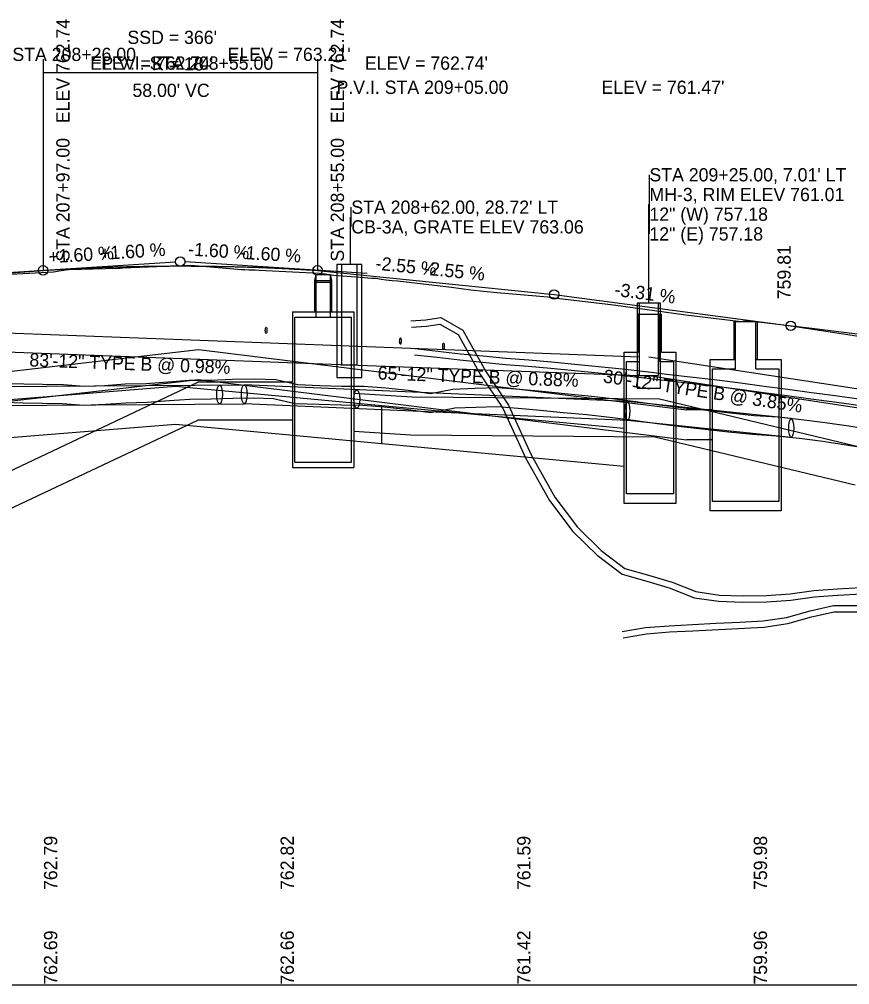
# Model space of a CAD drawing. Extents: x 1833473 to 1837132, y 704683 to 706683.
# Drawn here: x 1834502.8 to 1834678.2, y 705682.6 to 705886.7 of the extents above; entities that cross this region are included whole.
import ezdxf

# ---------------------------------------------------------------- set-up
doc = ezdxf.new("R2010")
doc.units = 0
for name, color, linetype in [('DR_P_Storm_Sewer', 7, 'Continuous'), ('DR_P_Text', 7, 'Continuous'), ('GK_Cells', 7, 'Continuous'), ('PF_P_Grade_Line', 7, 'Continuous'), ('PF_P_Text', 7, 'Continuous'), ('PF_X_Ground_Line', 7, 'Continuous'), ('PF_X_Text', 7, 'Continuous'), ('UT_P_Electric', 7, 'Continuous'), ('UT_P_Telecom', 7, 'Continuous'), ('UT_P_Water', 7, 'Continuous'), ('UT_X_Electric', 7, 'Continuous'), ('UT_X_Telecom', 7, 'Continuous'), ('UT_X_Water', 7, 'Continuous')]:
    doc.layers.add(name, color=color, linetype=linetype)

msp = doc.modelspace()

# ---------------------------------------------------------------- linework, layer by layer
at = {"layer": 'DR_P_Storm_Sewer'}
for p, q in [((1834572.78, 705834.89), (1834572.78, 705834.89)), ((1834635.78, 705826.69), (1834635.78, 705826.69)), ((1834486.63, 705820.89), (1834572.5, 705817.65)), ((1834486.63, 705816.89), (1834572.5, 705813.65)), ((1834572.5, 705817.65), (1834633.75, 705815.37)), ((1834635.78, 705815.37), (1834665.78, 705810.77)), ((1834572.5, 705813.65), (1834633.75, 705811.37)), ((1834635.78, 705811.37), (1834665.78, 705806.77)), ((1834665.78, 705810.77), (1834792.35, 705791.41)), ((1834665.78, 705806.77), (1834792.35, 705787.41))]:
    msp.add_line(p, q, dxfattribs=at)
for points in [[(1834569.88, 705834.89), (1834569.88, 705810.98), (1834575.14, 705810.98), (1834575.14, 705834.89), (1834569.88, 705834.89)], [(1834570.88, 705834.89), (1834570.88, 705813.65), (1834574.13, 705813.65), (1834574.13, 705834.89)], [(1834633.33, 705826.69), (1834633.33, 705808.7), (1834638.23, 705808.7), (1834638.23, 705826.69), (1834633.33, 705826.69)], [(1834633.75, 705826.69), (1834633.75, 705811.37), (1834637.81, 705811.37), (1834637.81, 705826.69)]]:
    msp.add_lwpolyline(points, dxfattribs=at)
at = {"layer": 'DR_P_Text'}
for p, q in [((1834635.85, 705853.82), (1834635.85, 705841.32)), ((1834572.85, 705846.97), (1834572.85, 705842.81))]:
    msp.add_line(p, q, dxfattribs=at)
for points in [[(1834635.78, 705826.69), (1834635.78, 705847.57), (1834635.85, 705847.57)], [(1834572.78, 705834.89), (1834572.78, 705844.89), (1834572.85, 705844.89)]]:
    msp.add_lwpolyline(points, dxfattribs=at)
at = {"layer": 'GK_Cells'}
msp.add_line((1833710.78, 705682.65), (1834910.78, 705682.65), dxfattribs=at)
msp.add_line((1833710.78, 705682.65), (1834910.78, 705682.65), dxfattribs=at)
at = {"layer": 'PF_P_Grade_Line'}
for p, q in [((1834457.78, 705829.97), (1834507.78, 705833.62)), ((1834565.78, 705833.62), (1834615.78, 705828.52)), ((1834615.78, 705828.52), (1834665.78, 705821.9)), ((1834665.78, 705821.9), (1834800.78, 705801.3))]:
    msp.add_line(p, q, dxfattribs=at)
msp.add_spline([(1834507.78, 705833.62), (1834508.94, 705833.69), (1834510.1, 705833.76), (1834511.26, 705833.83), (1834512.42, 705833.89), (1834513.58, 705833.95), (1834514.74, 705834.01), (1834515.9, 705834.07), (1834517.06, 705834.12), (1834518.22, 705834.17), (1834519.38, 705834.21), (1834520.54, 705834.26), (1834521.7, 705834.3), (1834522.86, 705834.33), (1834524.02, 705834.37), (1834525.18, 705834.4), (1834526.34, 705834.43), (1834527.5, 705834.45), (1834528.66, 705834.47), (1834529.82, 705834.49), (1834530.98, 705834.51), (1834532.14, 705834.52), (1834533.3, 705834.53), (1834534.46, 705834.54), (1834535.62, 705834.55), (1834536.78, 705834.55), (1834537.94, 705834.55), (1834539.1, 705834.54), (1834540.26, 705834.53), (1834541.42, 705834.52), (1834542.58, 705834.51), (1834543.74, 705834.49), (1834544.9, 705834.47), (1834546.06, 705834.45), (1834547.22, 705834.43), (1834548.38, 705834.4), (1834549.54, 705834.37), (1834550.7, 705834.33), (1834551.86, 705834.3), (1834553.02, 705834.26), (1834554.18, 705834.21), (1834555.34, 705834.17), (1834556.5, 705834.12), (1834557.66, 705834.07), (1834558.82, 705834.01), (1834559.98, 705833.95), (1834561.14, 705833.89), (1834562.3, 705833.83), (1834563.46, 705833.76), (1834564.62, 705833.69), (1834565.78, 705833.62)], degree=3, dxfattribs=at)
at = {"layer": 'PF_P_Text'}
for p, q in [((1834507.78, 705878.27), (1834507.78, 705833.62)), ((1834565.78, 705878.27), (1834565.78, 705833.62)), ((1834507.78, 705875.47), (1834565.78, 705875.47)), ((1834497.26, 705832.95), (1834535.78, 705835.41)), ((1834576.3, 705832.95), (1834537.78, 705835.41))]:
    msp.add_line(p, q, dxfattribs=at)
for centre in [(1834536.78, 705835.47), (1834507.78, 705833.62), (1834565.78, 705833.62), (1834615.78, 705828.52), (1834665.78, 705821.9)]:
    msp.add_circle(centre, 1, dxfattribs=at)
at = {"layer": 'PF_X_Ground_Line'}
for points in [[(1834498.28, 705832.64), (1834510.01, 705833.28), (1834510.85, 705833.43), (1834511.6, 705833.59), (1834512.07, 705833.68), (1834512.5, 705833.74), (1834512.9, 705833.78), (1834513.22, 705833.8), (1834523.55, 705834.09), (1834524.11, 705834.11), (1834524.63, 705834.13), (1834538.92, 705834.69), (1834547.31, 705834.03), (1834548.87, 705833.86), (1834549.74, 705833.8), (1834550.44, 705833.78), (1834551.24, 705833.76), (1834551.54, 705833.75), (1834551.85, 705833.74), (1834552.6, 705833.71), (1834553.46, 705833.68), (1834566.16, 705833.02), (1834566.74, 705832.96), (1834567.47, 705832.86), (1834568.28, 705832.75), (1834569.26, 705832.62), (1834570.13, 705832.52), (1834575.73, 705832.09), (1834576.39, 705832.02), (1834577.25, 705832), (1834578.15, 705831.97), (1834579.22, 705831.79), (1834580.26, 705831.62), (1834581.53, 705831.51), (1834582.78, 705831.4), (1834594.13, 705830.06), (1834598.17, 705829.52)], [(1834598.17, 705829.52), (1834603.7, 705828.97), (1834614.43, 705828), (1834615.82, 705827.84), (1834628.34, 705826.36), (1834643.65, 705824.23), (1834655.33, 705822.79), (1834656.45, 705822.99), (1834657.76, 705822.85), (1834667.83, 705821.66), (1834670.23, 705821.4), (1834680.37, 705820.12)]]:
    msp.add_lwpolyline(points, dxfattribs=at)
at = {"layer": 'UT_P_Electric'}
for p, q in [((1834653.81, 705814.8), (1834653.81, 705822.8)), ((1834653.81, 705822.8), (1834658.73, 705822.8)), ((1834654.14, 705812.8), (1834654.14, 705822.8)), ((1834658.39, 705812.8), (1834658.39, 705822.8)), ((1834658.73, 705814.8), (1834658.73, 705822.8)), ((1834392.11, 705799.79), (1834540.6, 705816.88)), ((1834540.6, 705816.88), (1834643.77, 705804.12)), ((1834649.27, 705784.8), (1834649.27, 705812.8)), ((1834649.27, 705812.8), (1834654.14, 705812.8)), ((1834658.39, 705812.8), (1834663.27, 705812.8)), ((1834663.27, 705812.8), (1834663.27, 705784.8)), ((1834392.11, 705793.46), (1834540.64, 705810.55)), ((1834540.64, 705810.55), (1834643.77, 705797.79)), ((1834649.27, 705804.12), (1834643.77, 705804.12)), ((1834649.27, 705797.79), (1834643.77, 705797.79)), ((1834663.27, 705784.8), (1834649.27, 705784.8))]:
    msp.add_line(p, q, dxfattribs=at)
msp.add_lwpolyline([(1834658.39, 705814.8), (1834663.77, 705814.8), (1834663.77, 705782.8), (1834648.77, 705782.8), (1834648.77, 705814.8), (1834654.14, 705814.8)], dxfattribs=at)
at = {"layer": 'UT_P_Telecom'}
for p, q in [((1834633.53, 705816.36), (1834633.53, 705824.36)), ((1834633.53, 705824.36), (1834638.45, 705824.36)), ((1834633.86, 705814.36), (1834633.86, 705824.36)), ((1834638.11, 705814.36), (1834638.11, 705824.36)), ((1834638.45, 705816.36), (1834638.45, 705824.36)), ((1834630.57, 705784.36), (1834630.57, 705816.36)), ((1834630.57, 705816.36), (1834633.53, 705816.36)), ((1834638.45, 705816.36), (1834641.49, 705816.36)), ((1834641.49, 705816.36), (1834641.49, 705784.36)), ((1834631.07, 705786.36), (1834631.07, 705814.36)), ((1834631.07, 705814.36), (1834633.86, 705814.36)), ((1834638.11, 705814.36), (1834640.99, 705814.36)), ((1834640.99, 705814.36), (1834640.99, 705786.36)), ((1834410.78, 705799.07), (1834535.78, 705809.12)), ((1834535.78, 705809.12), (1834630.55, 705800.27)), ((1834579.3, 705805.06), (1834579.3, 705797.06)), ((1834410.78, 705791.07), (1834535.78, 705801.12)), ((1834535.78, 705801.12), (1834630.55, 705792.27)), ((1834640.99, 705786.36), (1834631.07, 705786.36)), ((1834641.49, 705784.36), (1834630.57, 705784.36))]:
    msp.add_line(p, q, dxfattribs=at)
at = {"layer": 'UT_P_Water'}
for p, q in [((1834460.78, 705808.8), (1834550.3, 705809.43)), ((1834631.26, 705805.89), (1834550.3, 705809.43)), ((1834460.8, 705804.8), (1834550.3, 705805.43)), ((1834631.26, 705801.89), (1834550.3, 705805.43)), ((1834665.88, 705802.33), (1834631.26, 705805.89)), ((1834665.89, 705798.32), (1834631.26, 705801.89))]:
    msp.add_line(p, q, dxfattribs=at)
for centre, major_axis, ratio in [((1834545.09, 705807.39), (0, -2), 0.304231), ((1834550.3, 705807.43), (0, -2), 0.304231), ((1834574.1, 705806.39), (0, -2), 0.304231), ((1834631.26, 705803.86), (0, -1.96), 0.27031), ((1834665.89, 705800.29), (0, -1.96), 0.27031)]:
    msp.add_ellipse(centre, major_axis=major_axis, ratio=ratio, dxfattribs=at)
at = {"layer": 'UT_X_Electric'}
for p, q in [((1834565.25, 705831.5), (1834565.49, 705832.75)), ((1834565.49, 705823.73), (1834565.49, 705832.75)), ((1834565.49, 705832.75), (1834568.49, 705832.75)), ((1834568.49, 705832.75), (1834568.49, 705823.73)), ((1834568.49, 705832.75), (1834568.71, 705831.49)), ((1834565.25, 705824.83), (1834565.25, 705831.5)), ((1834565.25, 705831.5), (1834568.71, 705831.49)), ((1834565.25, 705831.09), (1834568.69, 705831.09)), ((1834568.71, 705831.49), (1834568.71, 705824.83)), ((1834560.49, 705824.83), (1834573.48, 705824.83)), ((1834560.49, 705824.83), (1834560.49, 705791.93)), ((1834573.48, 705824.83), (1834573.48, 705791.93)), ((1834560.99, 705823.73), (1834572.99, 705823.73)), ((1834560.99, 705793.07), (1834560.99, 705823.73)), ((1834572.99, 705793.07), (1834572.99, 705823.73)), ((1834500.49, 705791.07), (1834540.49, 705809.98)), ((1834560.49, 705809.98), (1834540.49, 705809.98)), ((1834500.49, 705783.06), (1834540.49, 705801.96)), ((1834560.49, 705801.96), (1834540.49, 705801.96)), ((1834560.49, 705791.93), (1834573.48, 705791.93)), ((1834560.99, 705793.07), (1834572.99, 705793.07))]:
    msp.add_line(p, q, dxfattribs=at)
for points in [[(1834585.53, 705822.92), (1834588.66, 705823.16), (1834591.86, 705823.67), (1834596.52, 705821.01), (1834601.38, 705812.23), (1834606.11, 705805.13), (1834610.92, 705794.63), (1834615.93, 705785.71), (1834620.75, 705779.34), (1834625.75, 705774.43), (1834630.75, 705770.62), (1834635.75, 705769.18), (1834640.74, 705767.71), (1834645.73, 705765.73), (1834650.71, 705765), (1834655.7, 705764.82), (1834660.69, 705764.92), (1834665.68, 705765.27), (1834670.67, 705765.93), (1834675.65, 705766.3), (1834680.62, 705766.58)], [(1834585.63, 705821.59), (1834588.82, 705821.84), (1834591.6, 705822.28), (1834595.53, 705820.04), (1834600.24, 705811.54), (1834604.94, 705804.48), (1834609.73, 705794.02), (1834614.82, 705784.98), (1834619.75, 705778.45), (1834624.88, 705773.42), (1834630.14, 705769.41), (1834635.37, 705767.9), (1834640.3, 705766.45), (1834645.38, 705764.43), (1834650.59, 705763.67), (1834655.69, 705763.48), (1834660.75, 705763.59), (1834665.81, 705763.94), (1834670.8, 705764.61), (1834675.74, 705764.97), (1834680.75, 705765.26)], [(1834573.48, 705807.65), (1834585.78, 705806.89)], [(1834585.78, 705806.89), (1834638.05, 705806.44), (1834681.25, 705796.1)], [(1834573.48, 705799.63), (1834585.5, 705798.89)], [(1834585.5, 705798.89), (1834637.07, 705798.45), (1834679.39, 705788.32)], [(1834630.16, 705757.26), (1834635.13, 705758.15), (1834640.09, 705758.52), (1834645.05, 705758.78), (1834650.02, 705759.04), (1834654.98, 705759.3), (1834659.95, 705759.56), (1834664.91, 705760.28), (1834669.88, 705761.65), (1834674.84, 705762.81), (1834679.83, 705762.78)], [(1834630.39, 705755.94), (1834635.29, 705756.82), (1834640.17, 705757.19), (1834645.12, 705757.45), (1834660.08, 705758.23), (1834665.19, 705758.98), (1834670.2, 705760.36), (1834674.99, 705761.47), (1834679.82, 705761.45)]]:
    msp.add_lwpolyline(points, dxfattribs=at)
for centre in [(1834583.3, 705818.67), (1834592.41, 705817.6)]:
    msp.add_ellipse(centre, major_axis=(0, -0.667), ratio=0.250004, dxfattribs=at)
at = {"layer": 'UT_X_Telecom'}
for points in [[(1834586.41, 705817.09), (1834591.2, 705816.57), (1834596, 705816.01), (1834600.81, 705815.56), (1834605.61, 705815.08), (1834610.41, 705814.69), (1834615.22, 705814.26), (1834620.19, 705813.8), (1834625.19, 705813.32), (1834630.19, 705812.8), (1834635.19, 705812.22), (1834640.19, 705811.64), (1834645.19, 705811.06), (1834650.19, 705810.47), (1834655.19, 705809.85), (1834660.19, 705809.13), (1834665.19, 705808.48), (1834670.19, 705807.81), (1834675.19, 705807.15), (1834680.19, 705806.49)], [(1834586.27, 705815.77), (1834591.05, 705815.25), (1834595.86, 705814.68), (1834600.68, 705814.23), (1834605.49, 705813.75), (1834610.3, 705813.36), (1834615.1, 705812.93), (1834620.07, 705812.48), (1834625.06, 705811.99), (1834630.05, 705811.48), (1834645.03, 705809.74), (1834650.03, 705809.14), (1834655.01, 705808.53), (1834660.01, 705807.81), (1834665.02, 705807.16), (1834670.01, 705806.49), (1834675.01, 705805.83), (1834680.01, 705805.16)]]:
    msp.add_lwpolyline(points, dxfattribs=at)
msp.add_ellipse((1834554.92, 705820.93), major_axis=(0, -0.667), ratio=0.250004, dxfattribs=at)
at = {"layer": 'UT_X_Water'}
for points in [[(1834499.89, 705809.74), (1834503.71, 705809.63), (1834507.67, 705809.57), (1834512.07, 705809.49), (1834516.45, 705809.16), (1834520.79, 705809.31), (1834525.12, 705809.62), (1834529.6, 705809.73), (1834534.12, 705810.07), (1834538.66, 705810.4), (1834543.21, 705810.44), (1834547.78, 705810.64), (1834552.37, 705810.67), (1834556.98, 705810.53), (1834561.61, 705809.47), (1834566.25, 705809.31), (1834570.9, 705809.17), (1834575.56, 705809.14), (1834580.25, 705808.77), (1834584.95, 705808.27), (1834589.65, 705807.62), (1834594.36, 705808.54), (1834599.07, 705808.69), (1834603.79, 705808.88), (1834608.51, 705808.5), (1834613.23, 705808.08), (1834618.08, 705807.57), (1834623.08, 705807.12), (1834628.08, 705806.56), (1834633.08, 705805.89)], [(1834499.59, 705805.75), (1834503.61, 705805.63), (1834507.61, 705805.57), (1834511.89, 705805.49), (1834516.37, 705805.16), (1834521, 705805.32), (1834525.31, 705805.62), (1834529.8, 705805.74), (1834534.41, 705806.08), (1834538.82, 705806.4), (1834543.31, 705806.44), (1834547.88, 705806.64), (1834552.32, 705806.67), (1834556.47, 705806.54), (1834561.09, 705805.48), (1834566.12, 705805.31), (1834570.83, 705805.17), (1834575.39, 705805.14), (1834579.88, 705804.78), (1834584.46, 705804.3), (1834589.76, 705803.57), (1834594.81, 705804.55), (1834599.22, 705804.69), (1834603.71, 705804.87), (1834608.18, 705804.51), (1834612.84, 705804.1), (1834617.69, 705803.58), (1834622.68, 705803.14), (1834627.59, 705802.59), (1834632.55, 705801.93)], [(1834633.08, 705805.89), (1834638.08, 705805.22), (1834643.08, 705804.59), (1834648.08, 705804.04), (1834653.08, 705803.5), (1834658.08, 705802.96), (1834663.08, 705802.63), (1834668.08, 705802.1), (1834673.08, 705801.47), (1834678.08, 705800.74), (1834683.08, 705799.92)], [(1834632.54, 705801.93), (1834637.56, 705801.25), (1834642.61, 705800.61), (1834647.65, 705800.07), (1834652.65, 705799.52), (1834657.73, 705798.98), (1834662.73, 705798.64), (1834667.62, 705798.13), (1834672.54, 705797.51), (1834677.47, 705796.78), (1834682.5, 705795.97)]]:
    msp.add_lwpolyline(points, dxfattribs=at)

# ---------------------------------------------------------------- texts
at = {"layer": 'DR_P_Text'}
for s, p in [("STA 209+25.00, 7.01' LT", (1834635.92, 705852.42)), ('MH-3, RIM ELEV 761.01', (1834635.92, 705848.25)), ("STA 208+62.00, 28.72' LT", (1834572.92, 705845.57)), ('12" (W) 757.18', (1834635.92, 705844.09)), ('CB-3A, GRATE ELEV 763.06', (1834572.92, 705841.41)), ('12" (E) 757.18', (1834635.92, 705839.92))]:
    msp.add_text(s, height=2.8, dxfattribs=at).set_placement(p)
for s, rotation, p in [('83\'-12" TYPE B @ 0.98%', 357.839, (1834504.86, 705813.33)), ('65\'-12" TYPE B @ 0.88%', 357.8683, (1834578.45, 705810.56)), ('30\'-12" TYPE B @ 3.85%', 351.2825, (1834626.03, 705809.96))]:
    msp.add_text(s, height=2.8, rotation=rotation, dxfattribs=at).set_placement(p)
at = {"layer": 'PF_P_Text'}
for s, rotation, p in [('STA 207+97.00   ELEV 762.74', 90, (1834513.38, 705835.47)), ('STA 208+55.00   ELEV 762.74', 90, (1834571.38, 705835.47)), ('+1.60 %', 3.6619, (1834519.91, 705835.8)), ('-1.60 %', 356.3381, (1834538.4, 705836.77)), ('759.81', 90, (1834665.78, 705827.5)), ('+1.60 %', 3.6619, (1834508.99, 705835.1)), ('-1.60 %', 356.3381, (1834549.32, 705836.08)), ('-2.55 %', 354.176, (1834577.96, 705833.78)), ('-2.55 %', 354.176, (1834588.16, 705832.74)), ('-3.31 %', 352.4585, (1834628.44, 705828.26)), ('762.79', 90, (1834510.78, 705702.65)), ('762.82', 90, (1834560.78, 705702.65)), ('761.59', 90, (1834610.78, 705702.65)), ('759.98', 90, (1834660.78, 705702.65))]:
    msp.add_text(s, height=2.8, rotation=rotation, dxfattribs=at).set_placement(p)
for s, p in [("SSD = 366'", (1834525.61, 705881.47)), ('P.V.I. STA 208+26.00', (1834491.1, 705877.87)), ("ELEV = 763.21'", (1834546.78, 705877.87)), ("ELEV = 762.74'", (1834517.78, 705876.02)), ('P.V.I. STA 208+55.00', (1834520.1, 705876.02)), ('K = 18', (1834530.81, 705875.87)), ("ELEV = 762.74'", (1834575.78, 705876.02)), ('P.V.I. STA 209+05.00', (1834569.79, 705870.92)), ("ELEV = 761.47'", (1834625.78, 705870.92)), ("58.00' VC", (1834526.67, 705870.27))]:
    msp.add_text(s, height=2.8, dxfattribs=at).set_placement(p)
at = {"layer": 'PF_X_Text'}
for s, p in [('762.69', (1834510.78, 705682.65)), ('762.66', (1834560.78, 705682.65)), ('761.42', (1834610.78, 705682.65)), ('759.96', (1834660.78, 705682.65))]:
    msp.add_text(s, height=2.8, rotation=90, dxfattribs=at).set_placement(p)

doc.saveas('drawing.dxf')
